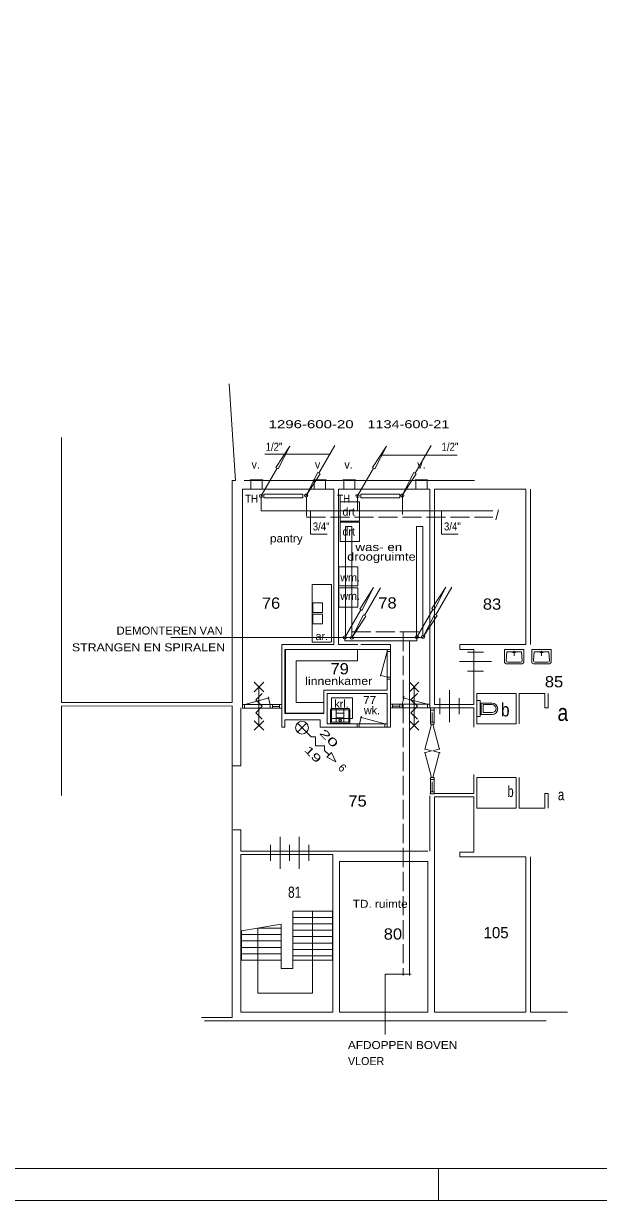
# Model space of a CAD drawing. Extents: x 295824 to 414724, y 24924 to 109024.
# Drawn here: x 338765 to 356725, y 24924 to 61673 of the extents above; entities that cross this region are included whole.
import ezdxf
from ezdxf.enums import TextEntityAlignment as Align

# ---------------------------------------------------------------- set-up
doc = ezdxf.new("R2010")
doc.units = 0
doc.header["$LTSCALE"] = 100
doc.linetypes.add('LONG_DASHED', pattern=[7.5, 6, -1.5])
doc.linetypes.add('MEDIUM_DASHED', pattern=[4.5, 3, -1.5])
for name, color, linetype, lineweight in [('1', 7, 'Continuous', 13), ('16', 7, 'Continuous', 13), ('61', 7, 'Continuous', 13)]:
    doc.layers.add(name, color=color, linetype=linetype, lineweight=lineweight)

msp = doc.modelspace()

# ---------------------------------------------------------------- linework, layer by layer
at = {"layer": '1'}
for p, q in [((351723.6, 24923.8), (351723.6, 25923.8)), ((304995.6, 24923.8), (414723.6, 24923.8))]:
    msp.add_line(p, q, dxfattribs=at)
msp.add_lwpolyline([(304995.6, 25923.8), (413723.6, 25923.8), (413723.6, 108023.8), (304995.6, 108023.8)], dxfattribs=at)
at = {"layer": '16'}
for p, q in [((348330.5, 48224), (346298.5, 48224)), ((348493.5, 48494.6), (347993.5, 47628.6)), ((349926.5, 48199.8), (352308.4, 48199.8)), ((351497.8, 48494.6), (350997.8, 47628.6)), ((346184.2, 46920.6), (346684.2, 47786.6)), ((349200.2, 46920.6), (349700.2, 47786.6)), ((349201.4, 46922.7), (349201.4, 46454.4)), ((353601.9, 46487.1), (353518.2, 46174.6)), ((349920.1, 44053.6), (349420.1, 43187.6)), ((352147.2, 44077.5), (351647.2, 43211.5)), ((348801.6, 42503.5), (349301.6, 43369.5)), ((351052.5, 42515.4), (351552.5, 43381.4)), ((343368.4, 42496.8), (351252.5, 42496.8)), ((348803.9, 42469.6), (348803.9, 42401.1)), ((348803.9, 42401.1), (351048.8, 42401.1)), ((350822.6, 42389.2), (350822.6, 31945.6)), ((351048.8, 42469.6), (351048.8, 42401.1))]:
    msp.add_line(p, q, dxfattribs=at)
at = {"layer": '16', "linetype": 'LONG_DASHED'}
for p, q in [((347599.8, 46886.3), (347599.8, 46254.4)), ((350602.8, 46945.4), (350602.8, 46254.4)), ((347599.8, 46254.4), (353422.1, 46254.4)), ((349017.3, 42680.4), (351244.4, 42680.4)), ((350622.6, 42680.4), (350622.6, 31945.6))]:
    msp.add_line(p, q, dxfattribs=at)
at = {"layer": '16'}
for points in [[(347084.2, 48479.6), (346720.2, 47765.6), (346648.2, 47807.6)], [(350100.2, 48479.6), (349736.2, 47765.6), (349664.2, 47807.6)], [(347593.5, 46935.6), (347957.5, 47649.6), (348029.5, 47607.6)], [(350597.8, 46935.6), (350961.8, 47649.6), (351033.8, 47607.6)], [(346274.2, 46866.4), (347490.9, 46866.4), (347490.9, 46973.6), (346274.2, 46973.6)], [(349302, 46866.4), (350518.7, 46866.4), (350518.7, 46973.6), (349302, 46973.6)], [(349701.6, 44062.5), (349337.6, 43348.5), (349265.6, 43390.5)], [(351952.5, 44074.4), (351588.5, 43360.4), (351516.5, 43402.4)], [(349020.1, 42494.6), (349384.1, 43208.6), (349456.1, 43166.6)], [(351247.2, 42518.5), (351611.2, 43232.5), (351683.2, 43190.5)]]:
    msp.add_lwpolyline(points, close=True, dxfattribs=at)
for points in [[(346184.2, 46920.3), (346184.2, 46454.4), (353422.1, 46454.4)], [(347729, 46446), (347729, 45732.8), (348247.4, 45732.8)], [(351826.5, 46446), (351826.5, 45732.8), (352344.9, 45732.8)], [(348821.9, 42537.4), (348821.9, 45969.3), (349024.4, 45969.3), (349024.4, 42549.3)], [(351037.1, 42537.4), (351037.1, 45969.3), (351239.5, 45969.3), (351239.5, 42549.3)], [(350872.8, 31992.9), (350063, 31992.9), (350063, 30110.1)]]:
    msp.add_lwpolyline(points, dxfattribs=at)
for centre in [(346184.2, 46920.3), (347593.5, 46935.9), (349200.2, 46920.3), (350597.8, 46935.9), (348801.6, 42503.2), (349020.1, 42494.9), (351052.5, 42515.1), (351247.2, 42518.8)]:
    msp.add_circle(centre, 50, dxfattribs=at)
at = {"layer": '61'}
for p, q in [((346235.9, 47420), (345842.7, 47420)), ((345842.7, 47420), (345842.7, 47402.5)), ((346235.9, 47420), (346235.9, 47402.5)), ((348214.2, 47420), (347821, 47420)), ((347821, 47420), (347821, 47402.5)), ((348214.2, 47420), (348214.2, 47402.5)), ((349136.6, 47420), (348743.4, 47420)), ((348743.4, 47420), (348743.4, 47402.5)), ((349136.6, 47420), (349136.6, 47402.5)), ((351387.8, 47420), (350994.5, 47420)), ((350994.5, 47420), (350994.5, 47402.5)), ((351387.8, 47420), (351387.8, 47402.5)), ((345604, 40407), (345604, 47132)), ((345654, 47402), (352855.2, 47402)), ((346235.9, 47402.5), (345842.7, 47402.5)), ((345866.7, 47402.5), (345866.7, 47131.5)), ((346216.7, 47400.3), (346216.7, 47131.5)), ((348214.2, 47402.5), (347821, 47402.5)), ((347845, 47402.5), (347845, 47131.5)), ((348195, 47400.3), (348195, 47131.5)), ((351458.4, 47132), (348604, 47132)), ((349127.9, 47131.5), (348604, 47131.5)), ((349136.6, 47402.5), (348743.4, 47402.5)), ((348767.4, 47402.5), (348767.4, 47131.5)), ((349117.4, 47400.3), (349117.4, 47131.5)), ((351379, 47131.5), (350985.8, 47131.5)), ((351387.8, 47402.5), (350994.5, 47402.5)), ((351018.6, 47402.5), (351018.6, 47131.5)), ((351368.6, 47400.3), (351368.6, 47131.5)), ((351458.4, 40407), (351458.4, 47132)), ((354604, 47132), (354604, 42282)), ((348379.2, 42357.2), (347782.1, 42357.2)), ((349304, 42282), (350227.6, 42282)), ((350227.6, 42282), (350227.6, 41198.3)), ((346929, 42132), (350228.6, 42132)), ((346929, 40127), (346929, 42132)), ((350127.9, 42061.7), (349921, 41289.5)), ((350127.6, 41198.3), (350127.6, 42132.3)), ((350227.6, 42132.3), (350127.6, 42132.3)), ((350227.7, 42065.3), (350127.6, 42065.3)), ((353129, 42049.1), (352629, 42049.1)), ((353862.1, 42057), (353841.1, 41782)), ((353866.1, 42057), (354316.1, 42057)), ((354041.1, 42032), (354141.1, 42032)), ((354041.1, 42032), (354141.1, 42032)), ((354091.1, 42082), (354091.1, 41932)), ((354091.1, 42082), (354091.1, 41957)), ((354320.1, 42057), (354341.1, 41782)), ((354715.2, 42057), (354694.2, 41782)), ((354719.2, 42057), (355169.2, 42057)), ((354894.2, 42032), (354994.2, 42032)), ((354894.2, 42032), (354994.2, 42032)), ((354944.2, 42082), (354944.2, 41932)), ((354944.2, 42082), (354944.2, 41957)), ((355173.2, 42057), (355194.2, 41782)), ((353379, 41749.1), (352379, 41749.1)), ((354341.1, 41682), (353841.1, 41682)), ((353891.1, 41732), (354291.1, 41732)), ((355194.2, 41682), (354694.2, 41682)), ((354744.2, 41732), (355144.2, 41732)), ((350127.9, 41264.3), (349900.5, 41325.2)), ((350227.6, 41198.3), (350127.6, 41198.3)), ((350227.5, 41265.3), (350128.1, 41265.3)), ((350229, 41195.8), (350229, 40407)), ((353129, 41449.1), (352629, 41449.1)), ((346268.2, 41104.8), (345968.2, 40804.8)), ((345968.2, 41104.8), (346268.2, 40804.8)), ((346118.2, 39754.8), (346118.2, 40954.8)), ((351117.8, 41104.8), (350817.8, 40804.8)), ((350817.8, 41104.8), (351117.8, 40804.8)), ((350967.8, 39754.8), (350967.8, 40954.8)), ((352069.9, 40861.2), (352069.9, 39861.2)), ((345672.8, 40410), (346440.1, 40615.6)), ((346467.4, 40407.8), (346402.3, 40650.5)), ((348386, 39971.8), (348386, 40621.8)), ((348390.3, 40621.6), (349040.3, 40621.6)), ((349038.6, 39971.8), (349038.6, 40621.8)), ((350590.8, 40413.8), (350655.9, 40656.5)), ((351385.4, 40416), (350618.1, 40621.6)), ((351769.9, 40611.2), (351769.9, 40111.2)), ((352369.9, 40611.2), (352369.9, 40111.2)), ((353399, 40456.1), (353029, 40456.1)), ((353059, 40456.1), (353059, 40096.1)), ((354249, 39807), (354249, 40757)), ((345670.2, 40299.8), (345670.2, 40409.8)), ((346470.2, 40299.8), (346470.2, 40409.8)), ((346537.2, 40299.8), (346537.2, 40409.8)), ((346538, 40350.6), (346762.7, 40350.6)), ((346762.7, 40299.8), (346762.7, 40409.8)), ((346829, 39707), (346829, 40307)), ((348350.6, 40246), (348350.6, 39831)), ((348925.6, 40281), (348385.6, 40281)), ((348385.6, 39871), (348385.6, 40231)), ((348400.6, 40246), (348910.6, 40246)), ((348535.6, 39856), (348535.6, 40281)), ((348775.6, 40139.3), (348535.6, 40139.3)), ((348775.6, 39856), (348775.6, 40281)), ((348925.6, 40231), (348925.6, 39871)), ((348960.6, 39831), (348960.6, 40246)), ((350229, 40307), (350229, 39707)), ((350295.5, 40305.8), (350295.5, 40415.8)), ((350520.2, 40356.6), (350295.5, 40356.6)), ((350521, 40305.8), (350521, 40415.8)), ((350588, 40305.8), (350588, 40415.8)), ((351388, 40305.8), (351388, 40415.8)), ((351588.8, 40305.3), (351454.6, 40305.3)), ((351472.8, 40305.3), (351472.8, 39795)), ((351472.8, 40303.7), (351586.7, 40303.7)), ((351473.6, 40236.7), (351587.6, 40236.7)), ((351588.9, 40307), (351588.9, 39795)), ((353399, 40096.1), (353029, 40096.1)), ((353119, 40156.1), (353119, 40406.1)), ((353119, 40406.1), (353409, 40406.1)), ((353119, 40156.1), (353399, 40156.1)), ((346268.2, 39904.8), (345968.2, 39604.8)), ((345968.2, 39904.8), (346268.2, 39604.8)), ((346929, 39707), (346829, 39707)), ((348029, 39927), (346929, 39927)), ((346929, 39707), (346929, 39927)), ((347604.9, 39825.5), (347322.1, 39542.7)), ((348029, 39707), (348029, 39927)), ((350229, 39707), (348029, 39707)), ((348950.6, 39856), (348360.6, 39856)), ((348360.6, 39821), (348950.6, 39821)), ((348390.3, 39972.8), (349040.3, 39972.8)), ((348775.6, 39997.6), (348535.6, 39997.6)), ((349185, 39707), (349185, 39806.3)), ((349252, 39710.3), (349252, 39806.3)), ((349254.8, 39804.3), (349319.9, 40047.1)), ((350049.4, 39806.5), (349282.1, 40012.1)), ((350052, 39707), (350052, 39806.3)), ((351117.8, 39904.8), (350817.8, 39604.8)), ((350817.8, 39904.8), (351117.8, 39604.8)), ((351509.7, 39794.9), (351298.2, 39005.6)), ((351472.8, 39795), (351588.9, 39795)), ((351473.6, 39862), (351587.6, 39862)), ((351762.9, 39007.8), (351552.1, 39794.2)), ((351288.6, 38904.6), (351510, 38963.9)), ((351296.8, 39022.7), (351509.4, 38965.8)), ((351551.8, 38963.8), (351780.7, 38902.5)), ((351552.2, 38966.8), (351774.1, 39026.3)), ((351509.8, 38134.8), (351297.9, 38925.9)), ((351763, 38921.9), (351552, 38134.6)), ((351472.8, 38135), (351588.9, 38135)), ((351472.8, 38135), (351472.8, 37621)), ((351473.6, 38068), (351587.6, 38068)), ((351588.9, 38135), (351588.9, 37621)), ((354249, 38127.6), (354249, 37177.6)), ((351452.3, 37621.1), (351602.3, 37621.1)), ((351452.9, 35827.6), (351452.9, 37558.2)), ((351472.8, 37621), (351586.7, 37621)), ((351473.6, 37688), (351586.7, 37688)), ((346477.4, 36027.6), (346477.4, 35527.6)), ((346777.4, 36277.6), (346777.4, 35277.6)), ((347077.4, 36027.6), (347077.4, 35527.6)), ((347377.4, 36277.6), (347377.4, 35277.6)), ((347677.4, 36027.6), (347677.4, 35527.6)), ((345554, 35827.6), (351394, 35827.6)), ((354604, 30802.6), (354604, 35652.6)), ((348415.1, 33961.9), (347175.2, 33961.9)), ((346811.5, 33549.5), (345571.7, 33338.3)), ((348415.1, 33761.9), (347175.2, 33761.9)), ((348415.1, 33561.9), (347175.2, 33561.9)), ((345571.7, 33338.3), (345571.7, 32425.5)), ((345571.7, 33225.5), (346811.5, 33225.5)), ((346083.6, 33425.5), (346811.5, 33425.5)), ((348415.1, 33361.9), (347175.2, 33361.9)), ((348415.1, 33161.9), (347175.2, 33161.9)), ((345571.7, 33025.5), (346811.5, 33025.5)), ((345571.7, 32825.5), (346811.5, 32825.5)), ((348415.1, 32961.9), (347175.2, 32961.9)), ((348415.1, 32761.9), (347175.2, 32761.9)), ((345571.7, 32625.5), (346811.5, 32625.5)), ((345571.7, 32425.5), (346811.5, 32425.5)), ((346811.5, 32425.5), (346811.5, 32167.6)), ((348415.1, 32561.9), (347175.2, 32561.9)), ((347175.2, 32425.5), (347175.2, 32167.6)), ((347175.2, 32167.6), (346811.5, 32167.6)), ((355092.3, 30532.6), (344422.7, 30532.6)), ((355752.4, 30802.6), (354604, 30802.6))]:
    msp.add_line(p, q, dxfattribs=at)
at = {"layer": '61', "linetype": 'MEDIUM_DASHED'}
for p, q in [((351533, 39863.7), (351533, 40235.2)), ((351533, 37695.3), (351533, 38066.9))]:
    msp.add_line(p, q, dxfattribs=at)
at = {"layer": '61'}
for points in [[(339953.7, 48744.2), (339953.7, 40468.1), (345284, 40468.1), (345284, 47402), (345383.4, 47402), (345188, 50426.2)], [(345604, 47132), (348454, 47132), (348454, 42282), (346829, 42282), (346829, 40407)], [(349204, 42282), (348604, 42282), (348604, 47132)], [(347782.1, 42357.2), (347782.1, 44157.2), (348382.1, 44157.2), (348382.1, 42363.8)], [(353791.1, 41732), (353791.1, 42132), (354391.1, 42132), (354391.1, 41732)], [(354644.2, 41732), (354644.2, 42132), (355244.2, 42132), (355244.2, 41732)], [(350129, 41200.2), (350129, 40857), (348149, 40857), (348149, 40127), (346929, 40127)], [(346218.2, 39954.8), (346018.2, 40154.8), (346218.2, 40354.8), (346018.2, 40554.8), (346218.2, 40754.8)], [(348249, 40757), (350129, 40757), (350129, 39707)], [(350129, 39807), (348249, 39807), (348249, 40757)], [(351067.8, 39954.8), (350867.8, 40154.8), (351067.8, 40354.8), (350867.8, 40554.8), (351067.8, 40754.8)], [(354249, 40757), (355049, 40757), (355049, 40307), (355149, 40307), (355149, 40757)], [(344322.7, 30632.6), (345284, 30632.6), (345284, 40368.1), (339953.7, 40360.1), (339953.7, 37568.1)], [(345554, 40307), (345554, 38497), (345283.5, 38497)], [(352829, 39707), (352829, 40307), (351588.9, 40307)], [(347322.1, 39825.5), (347746.4, 39401.2), (347887.8, 39401.2), (347887.8, 39118.4), (348170.6, 39118.4), (348170.6, 38977), (348312, 38835.5)], [(351604, 37627.6), (352829, 37627.6), (352829, 38227.6)], [(354249, 37177.6), (355049, 37177.6), (355049, 37627.6), (355149, 37627.6), (355149, 37177.6)], [(345309, 36497), (345554, 36497), (345554, 35827.6)], [(347786.9, 33961.9), (347786.9, 31401.2), (346084.1, 31401.2), (346084.1, 33425.6)], [(345571.7, 32425.5), (346811.5, 32425.5), (346811.5, 33549.5)]]:
    msp.add_lwpolyline(points, dxfattribs=at)
for points in [[(351604, 47132), (354454, 47132), (354454, 42282), (352394, 42282), (352394, 42132), (352829, 42132), (352829, 40407), (351604, 40407)], [(349255.2, 46137.5), (348655.2, 46137.5), (348655.2, 46737.5), (349255.2, 46737.5)], [(349255.2, 45503), (348655.2, 45503), (348655.2, 46103), (349255.2, 46103)], [(349210.7, 44110.1), (348610.7, 44110.1), (348610.7, 44710.1), (349210.7, 44710.1)], [(349210.7, 43448), (348610.7, 43448), (348610.7, 44048), (349210.7, 44048)], [(347807.1, 43282.2), (347807.1, 43582.2), (348107.1, 43582.2), (348107.1, 43282.2)], [(347807.1, 42931.8), (347807.1, 43231.8), (348107.1, 43231.8), (348107.1, 42931.8)], [(349197.7, 42122.7), (349197.7, 41778.1), (347286.1, 41778.1), (347286.1, 40477), (348144.4, 40477), (348144.4, 40137.8), (346944.4, 40137.8), (346944.4, 42122.7)], [(352929, 40757), (354149, 40757), (354149, 39807), (352929, 39807)], [(353029, 40531.1), (352929, 40531.1), (352929, 40031.1), (353029, 40031.1)], [(352929, 40531.1), (353029, 40531.1), (353029, 40031.1), (352929, 40031.1)], [(353029, 40531.1), (352929, 40531.1), (352929, 40031.1), (353029, 40031.1)], [(345604.3, 40300.1), (345604.3, 40410.5), (346828.6, 40410.5), (346828.6, 40300.1)], [(351453.9, 40306.2), (351453.9, 40416.5), (350229.6, 40416.5), (350229.6, 40306.2)], [(348241.3, 38764.8), (348382.8, 38906.2), (348524.2, 38623.4)], [(352929, 37177.6), (354149, 37177.6), (354149, 38127.6), (352929, 38127.6)], [(351604, 30802.6), (354454, 30802.6), (354454, 35652.6), (352394, 35652.6), (352394, 35802.6), (352829, 35802.6), (352829, 37527.6), (351604, 37527.6)], [(345554, 35727.6), (348424, 35727.6), (348424, 30802.6), (345554, 30802.6)], [(348634, 35507.6), (351394, 35507.6), (351394, 30802.6), (348634, 30802.6)], [(347175.2, 32425.5), (348415.1, 32425.5), (348415.1, 33961.9), (347175.2, 33961.9)]]:
    msp.add_lwpolyline(points, close=True, dxfattribs=at)
for centre, radius in [((347463.5, 39684.1), 200), ((348655.6, 39921), 40), ((348655.6, 39921), 30)]:
    msp.add_circle(centre, radius, dxfattribs=at)
for centre, radius, start, end in [((353841.1, 41732), 50, 180, 270), ((353891.1, 41782), 50, 180, 270), ((354291.1, 41782), 50, 270, 0), ((354341.1, 41732), 50, 270, 0), ((354694.2, 41732), 50, 180, 270), ((354744.2, 41782), 50, 180, 270), ((355144.2, 41782), 50, 270, 0), ((355194.2, 41732), 50, 270, 0), ((353399, 40276.1), 180, 270, 90), ((348385.6, 40246), 35, 90, 180), ((348400.6, 40231), 15, 90, 180), ((348910.6, 40231), 15, 0, 90), ((348925.6, 40246), 35, 0, 90), ((353399, 40281.1), 125, 270, 90), ((348360.6, 39846), 10, 90, 180), ((348360.6, 39831), 10, 180, 270), ((348400.6, 39871), 15, 180, 270), ((348910.6, 39871), 15, 270, 0), ((348950.6, 39846), 10, 0, 90), ((348950.6, 39831), 10, 270, 0)]:
    msp.add_arc(centre, radius, start, end, dxfattribs=at)

# ---------------------------------------------------------------- texts
at = {"layer": '16'}
for s, width, p in [('1296-600-20', 1.4, (346421.4, 49036.7)), ('1134-600-21', 1.35, (349508.1, 49036.7)), ('1/2"', 0.9, (346326.4, 48331.3)), ('1/2"', 0.9, (351822.9, 48331.3)), ('TH', 0.9, (345687.9, 46710.3)), ('TH', 0.9, (348562.5, 46710.3)), ('3/4"', 0.9, (347800.5, 45844.9)), ('3/4"', 0.9, (351898, 45844.9)), ('DEMONTEREN VAN', 1.05, (341671.2, 42593.6)), ('STRANGEN EN SPIRALEN', 1.15, (340277.8, 42069.3)), ('AFDOPPEN BOVEN', 1.1, (348899.9, 29651.9))]:
    msp.add_text(s, height=250, dxfattribs=dict(at, width=width)).set_placement(p)
msp.add_text('VLOER', height=250, dxfattribs=at).set_placement((348899.9, 29151.4))
at = {"layer": '61'}
for s, height, p in [('v.', 250, (345887.9, 47778.5)), ('v.', 250, (347866.1, 47778.5)), ('v.', 250, (348788.6, 47778.5)), ('v.', 250, (351063.6, 47778.5)), ('drt', 250, (348727.4, 46306.5)), ('drt', 250, (348727.4, 45685.8)), ('wm.', 250, (348660.7, 44252)), ('wm.', 250, (348660.7, 43672.7)), ('ar.', 250, (347886.1, 42420.8)), ('krl.', 250, (348476, 40306.2)), ('wk.', 250, (349399, 40104.2)), ('105', 350, (353135.9, 33111.3))]:
    msp.add_text(s, height=height, dxfattribs=at).set_placement(p)
for s, height, width, p in [('pantry', 250, 1.1, (346463.5, 45473.7)), ('was- en ', 250, 1.25, (349130.9, 45200.5)), ('droogruimte', 250, 1.2, (348875.3, 44902.5)), ('76', 350, 1.1, (346209.8, 43399.6)), ('78', 350, 1.1, (349847.7, 43407.1)), ('83', 350, 1.1, (353113.5, 43369.9)), ('79', 350, 1.1, (348353.9, 41351.2)), ('linnenkamer', 250, 1.15, (347563.9, 41019)), ('85', 350, 1.1, (355050.5, 40945.9)), ('77', 250, 1.1, (349373.2, 40424.6)), ('b', 350, 0.75, (353880.7, 37520.6)), ('75', 350, 1.1, (348912.4, 37222.7)), ('a', 350, 0.75, (355459, 37420.1)), ('81', 350, 0.8, (347026.7, 34374.5)), ('TD. ruimte', 250, 1.1, (349048.6, 34061.2)), ('80', 350, 1.1, (350017.5, 33070.4))]:
    msp.add_text(s, height=height, dxfattribs=dict(at, width=width)).set_placement(p)
at = {"layer": '61', "width": 0.85}
for s, height, p in [('b', 420, (353814.6, 40036.8)), ('a', 525, (355611.8, 39897.3))]:
    msp.add_text(s, height=height, dxfattribs=at).set_placement(p, align=Align.CENTER)
at = {"layer": '61'}
for s, width, p in [('20', 1.75, (347986.1, 39498.8)), ('19', 1.55, (347513.8, 38970.4))]:
    msp.add_text(s, height=250, rotation=315, dxfattribs=dict(at, width=width)).set_placement(p)
msp.add_text('6', height=250, rotation=315, dxfattribs=at).set_placement((348570, 38408.9))

doc.saveas('drawing.dxf')
